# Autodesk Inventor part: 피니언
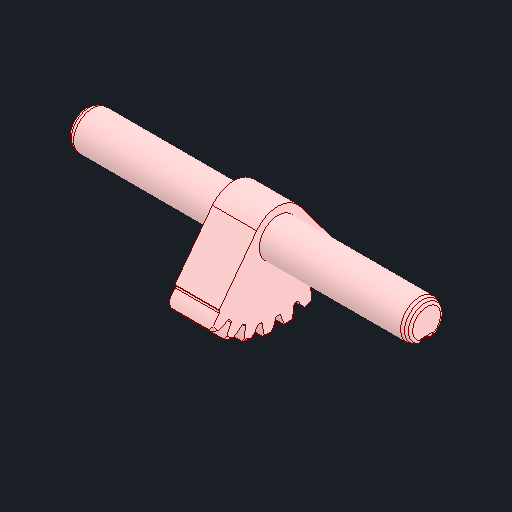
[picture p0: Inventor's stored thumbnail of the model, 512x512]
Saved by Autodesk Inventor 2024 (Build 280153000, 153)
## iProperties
Created: 2024-05
Part Number: 피니언
Material: 강철, 탄소
Document SubType Name: Modeling
Designer: kh_501
Density: 7.85 g/cm^3
Appearance: 기본값
Sending System: Autodesk Inventor 2025
Preprocessor: ST-DEVELOPER v20
Author: jhkim
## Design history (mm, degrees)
feature "솔리드1"
node "솔리드2"
